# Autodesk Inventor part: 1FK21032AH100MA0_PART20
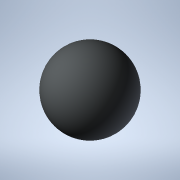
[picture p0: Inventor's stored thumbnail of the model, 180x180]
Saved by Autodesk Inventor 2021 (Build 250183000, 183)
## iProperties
Created: 2025-04
Part Number: 1FK21032AH100MA0_PART20
Material: Generic
Catalog Web Link: www.3dfindit.com
Description: -Servo synchronous motor
Document SubType Name: Modeling
Designer: psAdmin
Mass: 0.113097 g
Surface Area: 1.13097 cm^2
Volume: 0.113097 cm^3
Density: 1 g/cm^3
Appearance: PSOLRGB-212-217-219
Category: PARTsolutions
Title: 1FK21032AH100MA0_PART20
Author: Cadenas PARTsolutions
Comments: Servo synchronous motor
Sending System: PARTsolutions
Preprocessor: ST-DEVELOPER v19.3
PSOL_IDENT_0: {$CADENAS_DATA/23d-libs/siemens_ag/_cat_/12/33/1fk21032ah100ma0.prj},216 {VTYP=3D},{NB=1FK21032AH100
PSOL_IDENT_1: MA0_PART20},{LINA=1FK21032AH100MA0_PART20},{NN=1FK21032AH100MA0_PART20},{NOPRJ=TRUE},{DATE=19.08.202
PSOL_IDENT_2: 5 14:00:27},{GEOMDATE=30.07.2025 02:02:58},{VERSION=},{LINEID=10},{WBVAR=},{WBNUMERIC=}  {NB=1FK2103
PSOL_IDENT_3: 2AH100MA0_PART20},{LINA=1FK21032AH100MA0_PART20},{KT=DUMMY},{PREVIEW=../../../_pool_/d3/78/p_d211_xx
PSOL_IDENT_4: _00934j.png},{DESCSHORT=SIMOTICS S-1FK2 HD, SINAMICS S210 3AC 400V-480V, 0.59 Nm, 4500 rpm},{DESCLON
PSOL_IDENT_5: G=SIMOTICS S-1FK2 HD servo motor M0=0.64 Nm; PN = 0.28 kW at nN=4500 rpm (380-480 V); PN = 0.167 kW
PSOL_IDENT_6: at nN=2500 rpm (200-240 V); with holding brake; degree of protection IP64; cylindrical shaft D14 x 3
PSOL_IDENT_7: 0 mm; absolute encoder 22-bit + 12-bit multiturn (encoder AM22DQC); with OCC interface; plug size M1
PSOL_IDENT_8: 7, rotatable; SIMOTICS S-1FK2 servomotorfor a wide range of uses in industrial environments. SIMOTIC
PSOL_IDENT_9: S S‑1FK2 servomotors are compact synchronous motors with a high dynamic performance that set themsel
PSOL_IDENT_10: ves apart as a result of their high power density, degree of protection and overload capability. The
PSOL_IDENT_11: motors are available in two variants: as High Dynamic variant (highest dynamic performance as a res
PSOL_IDENT_12: ult of the low intrinsic moment of inertia for applications demanding a high dynamic performance wit
PSOL_IDENT_13: h low moved masses) - and as Compact variant (precise and stable closed-loop control for medium up t
PSOL_IDENT_14: o large moved masses as a result of a medium intrinsic moment of inertia). SIMOTICSS‑1FK2 servomotor
PSOL_IDENT_15: s fully exploit their strengths in a system with the SINAMICSS210 frequency converter and simple con
PSOL_IDENT_16: nection using the one cable connection (OCC). Advantages include the short control and positioning t
PSOL_IDENT_17: imes, fast and precise correction of disturbing quantities as well as stable control with a high dyn
PSOL_IDENT_18: amic performance. The servo motors can be configured to address a wide range of requirements. For ex
PSOL_IDENT_19: ample with and without holding brake, IP64 or IP65 degree of protection, singleturn or multiturn abs
PSOL_IDENT_20: olute encoders - to name just a few. Further, the servomotors are available in different shaft heigh
PSOL_IDENT_21: ts extending from 20 to 100. A shaft sealing ring is available to achieve an IP65 degree of protecti
PSOL_IDENT_22: on and for subsequent mounting at the motor or as spare part. SIMOTICS - the optimum motor for each
PSOL_IDENT_23: and every motion control application.},{INTNO=195125315563},{SUPPLIERALTNO=1FK2103-2AH10-0MA0},{MANU
PSOL_IDENT_24: ID=1FK21032AH100MA0},{MANUNAME=Siemens},{MANUTYPEDESC=SYNCHRONOUS MOTOR 1FK2 HD 0,64 NM},{AAU732=SIM
PSOL_IDENT_25: OTICS},{AAO057=S-1FK2},{AAU734=SIMOTICS S-1FK2 HD servo motor M0=0.64 Nm; PN = 0.28 kW at nN=4500 rp
PSOL_IDENT_26: m (380-480 V); PN = 0.167 kW at nN=2500 rpm (200-240 V); with holding brake; degree of protection IP
PSOL_IDENT_27: 64; cylindrical shaft D14 x 30 mm; absolute encoder 22-bit + 12-bit multiturn (encoder AM22DQC); wit
PSOL_IDENT_28: h OCC interface; plug size M17, rotatable;},{AAW338=SYNCHRONOUS MOTOR 1FK2 HD 0,64 NM},{AAO742=SIMOT
PSOL_IDENT_29: ICS},{AAO663=4034106444723},{NOCUPEROU=1},{PRICEQUANTITY=1},{QUANTITYMIN=1},{QUANTITYINT=1},{CTN=850
PSOL_IDENT_30: 15100},{COO=RO},{AAO676=1FK2103-2AH10-0MA0},{AAO677=Siemens AG},{ORDERUNIT=C62},{CONTENTUNIT=C62}
NB: 1FK21032AH100MA0_PART20
NT: Servo synchronous motor
NBSYN: $MANUID._PART20
LINA: 1FK21032AH100MA0_PART20
CATALOG: SIEMENS
PREVIEW: ../../../_pool_/d3/78/p_d211_xx_00934j.png
DESCSHORT: SIMOTICS S-1FK2 HD, SINAMICS S210 3AC 400V-480V, 0.59 Nm, 4500 rpm
DESCLONG: SIMOTICS S-1FK2 HD servo motor M0=0.64 Nm; PN = 0.28 kW at nN=4500 rpm (380-480 V); PN = 0.167 kW at nN=2500 rpm (200-240 V); with holding brake; degree of prot
INTNO: 195125315563
SUPPLIERALTNO: 1FK2103-2AH10-0MA0
MANUID: 1FK21032AH100MA0
MANUNAME: Siemens
MANUTYPEDESC: SYNCHRONOUS MOTOR 1FK2 HD 0,64 NM
AAU732: SIMOTICS
AAO057: S-1FK2
AAU734: SIMOTICS S-1FK2 HD servo motor M0=0.64 Nm; PN = 0.28 kW at nN=4500 rpm (380-480 V); PN = 0.167 kW at nN=2500 rpm (200-240 V); with holding brake; degree of prot
AAW338: SYNCHRONOUS MOTOR 1FK2 HD 0,64 NM
AAO742: SIMOTICS
AAO663: 4034106444723.0
NOCUPEROU: 1
PRICEQUANTITY: 1
QUANTITYMIN: 1
QUANTITYINT: 1
CTN: 85015100
COO: RO
ARTICLENO: 1FK21032AH100MA0_PART20
BOMINFO: 1FK21032AH100MA0_PART20
CREATOR: CADENAS GmbH
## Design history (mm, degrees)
feature "2025_04_17_15_06_16_0705"
body "Solid1"
